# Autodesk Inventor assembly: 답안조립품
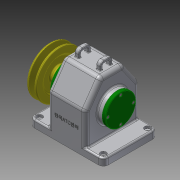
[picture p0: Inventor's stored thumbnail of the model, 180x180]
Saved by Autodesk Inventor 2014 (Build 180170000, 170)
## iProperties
Created: 2016-12
Part Number: 답안조립품
Document SubType Name: Assembly
Designer: USER
Author: USER
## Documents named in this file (15)
- C:\Users\USER\Desktop\461208V1021\답안조립품.iam
- C:\Users\USER\Desktop\461208V1021\본체.ipt
- C:\Users\USER\Desktop\461208V1021\V-벨트풀리.ipt
- C:\Users\USER\Desktop\461208V1021\뒤커버.ipt
- C:\Users\USER\Desktop\461208V1021\멈춤나사 - M4x10.ipt
- C:\Users\USER\Desktop\461208V1021\베어링 6203.ipt
- C:\Users\USER\Desktop\461208V1021\볼트 M3 x 8.ipt
- C:\Users\USER\Desktop\461208V1021\볼트 M3 x 10.ipt
- C:\Users\USER\Desktop\461208V1021\부시.ipt
- C:\Users\USER\Desktop\461208V1021\스퍼기어.ipt
- C:\Users\USER\Desktop\461208V1021\앞커버.ipt
- C:\Users\USER\Desktop\461208V1021\오일씰 28 40 8.ipt
- C:\Users\USER\Desktop\461208V1021\축.ipt
- C:\Users\USER\Desktop\461208V1021\키 - 5 x 5 x 18.ipt
- C:\Users\USER\Desktop\461208V1021\키 - 6 x 6 x 22.ipt
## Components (9 placed, 3 different names)
1. V-벨트풀리:1
2. ISO 4762 M3 x 8:1
3. ISO 4762 M3 x 8:2
4. ISO 4762 M3 x 8:3
5. ISO 4762 M3 x 8:4
6. ISO 4762 M3 x 10:1
7. ISO 4762 M3 x 10:2
8. ISO 4762 M3 x 10:3
9. ISO 4762 M3 x 10:4
